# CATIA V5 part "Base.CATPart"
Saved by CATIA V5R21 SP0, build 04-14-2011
Part number: Part1
Bounding box of the stored display mesh (mm): x -50 to 50, y -25 to 25, z 0 to 50
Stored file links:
  D:\CATIA V5R21 E-RESOURCES\CATIA-V5R21\catia-v5r21-prt\c12-catia-v5r20-prt\c12-catia-v5-r20-figr-12-8\cat_v5r21_Base.CATPart
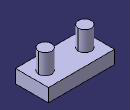
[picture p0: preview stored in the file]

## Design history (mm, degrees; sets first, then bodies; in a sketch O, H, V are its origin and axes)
Body1 (main body)
  Sketch1 on xy-plane, origin (0, 0, 0), H (1, 0, 0), V (0, 1, 0)
    line L1 (50, 25) -> (50, -25)
    line L2 (50, -25) -> (-50, -25)
    line L3 (-50, -25) -> (-50, 25)
    line L4 (-50, 25) -> (50, 25)
    circle A1 centre (-30, 0) radius 10
    point P5 (-30, 0)
    circle A2 centre (30, 0) radius 10
    length L2 = 100
    length L1 = 50
    radius A1 = 10
    distance P5 V = 30
    vertical: L1 V, L3 V
    horizontal: L2 H, L4 H
    equidistance: L1 L3 O, L2 L4 O
    coincidence: P5 H
    symmetry: A1 A2 V
  MultiPad1: profile Sketch1, domains (length 20; length 50; length 50)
